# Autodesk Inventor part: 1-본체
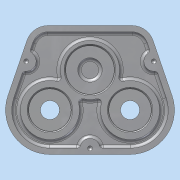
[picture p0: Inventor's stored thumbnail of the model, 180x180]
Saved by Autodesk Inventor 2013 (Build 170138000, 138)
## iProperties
Created: 2014-12
Part Number: 1-본체
Material: 알루미늄 6061
Document SubType Name: Modeling
Designer: WINDOWS7
Density: 2.71 g/cm^3
Mass: 605.676 g
Surface Area: 658.163 cm^2
Volume: 223.497 cm^3
Author: WINDOWS7
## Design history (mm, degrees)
sketch "스케치1"
  geometry: L1 (-32.527, -32.527)-(32.527, -32.527); L2 (-47, 36)-(47, 36); L3 (-32.527, -68.527)-(32.527, -68.527); L4 (-47, 36)-(-66.565, -20.803); L5 (47, 36)-(66.565, -20.803); A1 r 46 centre (0, 0) between (-32.527, -32.527) and (32.527, -32.527); A2 r 36 centre (-32.527, -32.527) between (-32.527, -68.527) and (-66.565, -20.803); A3 r 36 centre (32.527, -32.527) between (32.527, -68.527) and (66.565, -20.803); 2 further points
  constraints: 10 end point, 6 point on circle, 3 centre point, 2 horizontal, 2 tangent, 1 coincident, 1 equal length, 1 equal radius, 1 horizontal alignment, 1 midpoint, 1 parallel, 1 vertical alignment
  dimensions: "d1" = 72 diameter of A2; "d2" = 90 deg dimension on point (0, 0) L1.end L1.start; "d3" = 94 distance of L2.start L2.end; "d4" = 36 distance of point (0, 0) point (0, 36); "d58" = 92 diameter of A1
extrude "돌출1" new body sketch "스케치1" distance "d5" = 44; taper "d6" = 0 deg
fillet "모깎기1" dims "d7" = 18
sketch "스케치2"
  geometry: L1 (34.162, 36)-(-34.162, 36) reference; L2 (-51.181, 23.862)-(-66.565, -20.803) reference; L3 (-32.527, -68.527)-(32.527, -68.527) reference; L4 (66.565, -20.803)-(51.181, 23.862) reference; L5 (-34.162, 31)-(34.162, 31); L6 (46.453, 22.233)-(61.837, -22.432); L7 (32.527, -63.527)-(-32.527, -63.527); L8 (-61.837, -22.432)-(-46.453, 22.233); A1 r 18 centre (34.162, 18) between (51.181, 23.862) and (34.162, 36) reference; A2 r 18 centre (-34.162, 18) between (-34.162, 36) and (-51.181, 23.862) reference; A3 r 36 centre (-32.527, -32.527) between (-66.565, -20.803) and (-32.527, -68.527) reference; A4 r 36 centre (32.527, -32.527) between (32.527, -68.527) and (66.565, -20.803) reference; A5 r 13 centre (34.162, 18) between (46.453, 22.233) and (34.162, 31); A6 r 31 centre (32.527, -32.527) between (32.527, -63.527) and (61.837, -22.432); A7 r 31 centre (-32.527, -32.527) between (-61.837, -22.432) and (-32.527, -63.527); A8 r 13 centre (-34.162, 18) between (-34.162, 31) and (-46.453, 22.233); A9 r 8 centre (51.7, 7) between (49.095, 14.564) and (54.305, -0.564); A10 r 8 centre (-51.7, 7) between (-54.305, -0.564) and (-49.095, 14.564); A11 r 8 centre (0, -63.527) between (8, -63.527) and (-8, -63.527); 1 further point
  constraints: 14 point on circle, 8 end point, 8 point on line, 7 centre point, 2 equal radius, 1 horizontal alignment, 1 midpoint, 7 other
  dimensions: "d8" = 5 distance between parallel lines of L5 L1; "d9" = 29 distance from line of A9.centre L1; "d10" = 16 diameter of A9
extrude "돌출2" cut sketch "스케치2" distance "d11" = 34; taper "d12" = 0 deg
fillet "모깎기2" dims "d13" = 3
sketch "스케치3"
  geometry: C1 r 24 at (-32.527, -32.527); C2 r 24 at (0, 0); C3 r 24 at (32.527, -32.527); A1 r 31 centre (-32.527, -32.527) between (-61.837, -22.432) and (-32.527, -63.527) reference; A2 r 31 centre (32.527, -32.527) between (32.527, -63.527) and (61.837, -22.432) reference; 1 further point
  constraints: 3 centre point, 3 coincident, 2 equal radius
  dimensions: "d14" = 48 diameter of C2
extrude "돌출3" join sketch "스케치3" distance "d16" = 11; taper "d17" = 0 deg
fillet "모깎기3" dims "d18" = 3
fillet "모깎기4" dims "d19" = 3
sketch "스케치4"
  geometry: C1 r 20 at (-32.527, -32.527); C2 r 20 at (32.527, -32.527); A1 r 33 centre (-32.527, -32.527) between (-63.728, -21.78) and (-32.527, -65.527) reference; A2 r 33 centre (32.527, -32.527) between (32.527, -65.527) and (63.728, -21.78) reference; 1 further point
  constraints: 2 centre point, 2 coincident, 1 equal radius
  dimensions: "d20" = 40 diameter of C1
extrude "돌출4" join sketch "스케치4" distance "d22" = 7; taper "d23" = -10 deg
fillet "모깎기5" dims "d24" = 3
sketch "스케치5"
  geometry: C1 r 17.5 at (-32.527, -32.527); C2 r 17.5 at (32.527, -32.527); A1 r 24 centre (-32.527, -32.527) between (-26.959, -9.182) and (-9.182, -26.959) reference; A2 r 24 centre (32.527, -32.527) between (9.182, -26.959) and (26.959, -9.182) reference
  constraints: 2 centre point, 2 coincident, 1 equal radius
  dimensions: "d25" = 35 diameter of C1
extrude "돌출5" cut sketch "스케치5" distance "d27" = 11; taper "d28" = 0 deg
sketch "스케치6"
  geometry: C1 r 20 at (0, 0); A1 r 24 centre (0, 0) between (23.345, -5.568) and (-23.345, -5.568) reference
  constraints: 1 centre point, 1 coincident
  dimensions: "d29" = 40 diameter of C1
extrude "돌출6" cut sketch "스케치6" distance "d30" = 12; taper "d31" = 0 deg
sketch "스케치7"
  geometry: C1 r 20 at (0, 0) reference; C2 r 10 at (0, 0)
  constraints: 1 centre point, 1 coincident
  dimensions: "d32" = 20 diameter of C2
extrude "돌출7" cut sketch "스케치7" distance "d33" = 3; taper "d34" = 0 deg
sketch "스케치8"
  geometry: C1 r 17.5 at (0, 0) reference; C2 r 7.75 at (0, 0); C3 r 17.5 at (65.054, 0) reference; C4 r 7.75 at (65.054, 0); 1 further point
  constraints: 2 centre point, 2 coincident, 1 equal radius
  dimensions: "d35" = 15.5 diameter of C2
extrude "돌출8" cut sketch "스케치8" distance "d36" = 10; taper "d37" = 0 deg
sketch "스케치9"
  geometry: C1 r 7.75 at (0, 0) reference; C2 r 15 at (0, 0); C3 r 17.5 at (65.054, 0) reference; C4 r 15 at (65.054, 0); 1 further point
  constraints: 2 centre point, 2 coincident, 1 equal radius
  dimensions: "d38" = 30 diameter of C2
extrude "돌출9" cut sketch "스케치9" distance "d39" = 7; taper "d40" = 0 deg
chamfer "모따기1" distance "d41" = 1; stored, may be unused: second distance "d42" = 2, angle "d43" = 45 deg
fillet "모깎기6" dims "d44" = 3, "d45" = 0.3, "d46" = 0.1
fillet "모깎기7" dims "d47" = 3
sketch "스케치10"
  geometry: A1 r 8 centre (51.7, 7) between (47.131, 13.567) and (52.144, -0.988) reference; A2 r 8 centre (0, -63.527) between (7.697, -61.345) and (-7.697, -61.345) reference; A3 r 8 centre (-51.7, 7) between (-52.144, -0.988) and (-47.131, 13.567) reference; 4 further points
  constraints: 3 coincident
hole "구멍1" sketch "스케치10" at (-51.7, 7), (51.7, 7), (0, -63.527) diameter "d48" = 4.134; stored, may be unused: countersink angle "d52" = 90 deg, drill point angle "d54" = 118 deg; dims "d49" = 20, "d50" = 4, "d51" = 2, "d53" = 23
sketch "스케치11"
  geometry: L1 (34.162, 36)-(-34.162, 36) reference; 2 further points
  constraints: 1 vertical alignment, 1 other
  dimensions: "d55" = 30 distance from line of point (0, 6) L1
feature "엠보싱1" sketch "스케치11" dims "d1" = 72, "d2" = 90 deg, "d3" = 94, "d4" = 36, "d56" = 1, "d57" = 0, "d58" = 92
node "솔리드1"
node "투영된 루프1"
